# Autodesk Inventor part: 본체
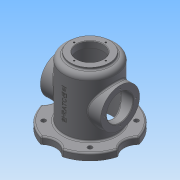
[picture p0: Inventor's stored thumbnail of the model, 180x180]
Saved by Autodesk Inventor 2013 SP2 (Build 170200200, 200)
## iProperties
Created: 2026-07
Part Number: 본체
Material: Generic
Document SubType Name: Modeling
Designer: a
Density: 1 g/cm^3
Mass: 556.956 g
Surface Area: 1242.71 cm^2
Volume: 556.956 cm^3
Author: a
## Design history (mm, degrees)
sketch "스케치1"
  geometry: L1 (100, 0)-(-100, 0); L2 (0, -100)-(0, 100); A1 r 30 centre (100, 0) between (79.12, -21.541) and (79.12, 21.541); A2 r 30 centre (0, 100) between (-21.541, 79.12) and (21.541, 79.12); A3 r 30 centre (-100, 0) between (-79.12, -21.541) and (-79.12, 21.541); A4 r 30 centre (0, -100) between (21.541, -79.12) and (-21.541, -79.12); A5 r 82 centre (0, 0) between (21.541, -79.12) and (79.12, -21.541); A6 r 82 centre (0, 0) between (-79.12, -21.541) and (-21.541, -79.12); A7 r 82 centre (0, 0) between (79.12, 21.541) and (21.541, 79.12); A8 r 82 centre (0, 0) between (-21.541, 79.12) and (-79.12, 21.541); 3 further points
  constraints: 16 point on circle, 8 centre point, 4 coincident, 4 end point, 4 midpoint, 1 horizontal, 1 perpendicular, 9 other
  dimensions: "d1" = 200 distance of L1.start L1.end; "d2" = 200 distance of L2.start L2.end; "d3" = 60 diameter of A1; "d6" = 360 deg dimension on A5.centre A1.centre (derived); "d8" = 82 radius of A5; "d9" = 82 radius of A6; "d10" = 82 radius of A8; "d11" = 82 radius of A7
extrude "돌출1" new body sketch "스케치1" distance "d12" = 14; taper "d13" = 0 deg
sketch "스케치2"
  geometry: C1 r 53 at (0, 0); 1 further point
  constraints: 1 centre point, 1 coincident
  dimensions: "d14" = 106 diameter of C1
extrude "돌출2" join sketch "스케치2" distance "d15" = 132; taper "d16" = 0 deg
sketch "스케치3"
  geometry: C1 r 53 at (0, 0) reference; C2 r 40 at (0, 0)
  constraints: 1 centre point, 1 coincident
  dimensions: "d17" = 80 diameter of C2
extrude "돌출3" join sketch "스케치3" distance "d18" = 5; taper "d19" = 0 deg
sketch "스케치4"
  geometry: L1 (-70, 0)-(-70, 14) reference; L2 (-70, 14)-(-53, 14) reference; L3 (-53, 14)-(-53, 132) reference; L4 (-53, 132)-(-40, 132) reference; L5 (-40, 132)-(-40, 137) reference; L6 (-40, 137)-(40, 137) reference; L7 (40, 137)-(40, 132) reference; L8 (40, 132)-(53, 132) reference; L9 (53, 132)-(53, 14) reference; L10 (53, 14)-(70, 14) reference; L11 (70, 14)-(70, 0) reference; L12 (70, 0)-(-70, 0) reference; L13 (-62, 68)-(62, 68); L14 (-62, 68)-(-62, 108); L15 (-62, 108)-(62, 108); L16 (62, 108)-(62, 68); 3 further points
  constraints: 8 end point, 2 midpoint, 2 parallel, 2 perpendicular, 1 vertical alignment
  dimensions: "d20" = 68 distance from line of point (0, 0) L13; "d21" = 124 distance of L13.start L13.end; "d22" = 80 diameter of L15 L13
revolve "회전1" sketch "스케치4" stored, may be unused: angle "d23" = 90 deg
sketch "스케치5"
  geometry: L1 (-70, 0)-(-70, 14) reference; L2 (-70, 14)-(-53, 14) reference; L3 (-53, 14)-(-53, 28) reference; L4 (-53, 28)-(-62, 28) reference; L5 (-62, 28)-(-62, 108) reference; L6 (-62, 108)-(-53, 108) reference; L7 (-53, 108)-(-53, 132) reference; L8 (-53, 132)-(-40, 132) reference; L9 (-40, 132)-(-40, 137) reference; L10 (-40, 137)-(40, 137) reference; L11 (40, 137)-(40, 132) reference; L12 (40, 132)-(53, 132) reference; L13 (53, 132)-(53, 108) reference; L14 (53, 108)-(62, 108) reference; L15 (62, 108)-(62, 28) reference; L16 (62, 28)-(53, 28) reference; L17 (53, 28)-(53, 14) reference; L18 (53, 14)-(70, 14) reference; L19 (70, 14)-(70, 0) reference; L20 (70, 0)-(-70, 0) reference; L21 (0, 0)-(0, 137); L22 (-27, 137)-(-27, 124); L23 (-27, 124)-(-42, 124); L24 (-45, 121)-(-45, 0); L25 (-27, 137)-(0, 137); L26 (-45, 0)-(0, 0); A1 r 3 centre (-42, 121) between (-42, 124) and (-45, 121)
  constraints: 12 end point, 2 perpendicular, 2 point on circle, 2 point on line, 2 tangent, 1 centre point, 1 collinear, 1 midpoint, 1 parallel, 1 vertical
  dimensions: "d24" = 54 diameter of L22 L21; "d26" = 90 diameter of L24 L21; "d27" = 124 distance between parallel lines of L20 L23; "d28" = 3 radius of A1
revolve "회전2" sketch "스케치5" stored, may be unused: angle "d29" = 90 deg
chamfer "모따기1" distance "d30" = 1; stored, may be unused: second distance "d31" = 2, angle "d32" = 45 deg
sketch "스케치6"
  geometry: L1 (70, 14)-(70, 0) reference; L2 (70, 0)-(45, 0) reference; L3 (45, 0)-(45, 121) reference; L4 (42, 124)-(27, 124) reference; L5 (27, 124)-(27, 136) reference; L6 (27, 136)-(28, 137) reference; L7 (28, 137)-(40, 137) reference; L8 (40, 137)-(40, 132) reference; L9 (40, 132)-(53, 132) reference; L10 (53, 132)-(53, 108) reference; L11 (53, 108)-(62, 108) reference; L12 (62, 108)-(62, 28) reference; L13 (62, 28)-(53, 28) reference; L14 (53, 28)-(53, 14) reference; L15 (53, 14)-(70, 14) reference; L16 (-70, 0)-(-70, 14) reference; L17 (-70, 14)-(-53, 14) reference; L18 (-53, 14)-(-53, 28) reference; L19 (-53, 28)-(-62, 28) reference; L20 (-62, 28)-(-62, 108) reference; L21 (-62, 108)-(-53, 108) reference; L22 (-53, 108)-(-53, 132) reference; L23 (-53, 132)-(-40, 132) reference; L24 (-40, 132)-(-40, 137) reference; L25 (-40, 137)-(-28, 137) reference; L26 (-28, 137)-(-27, 136) reference; L27 (-27, 136)-(-27, 124) reference; L28 (-27, 124)-(-42, 124) reference; L29 (-45, 121)-(-45, 0) reference; L30 (-45, 0)-(-70, 0) reference; L31 (-62, 68)-(62, 68); L32 (-62, 68)-(-62, 95); L33 (-62, 95)-(62, 95); L34 (62, 95)-(62, 68); A1 r 3 centre (42, 121) between (45, 121) and (42, 124) reference; A2 r 3 centre (-42, 121) between (-42, 124) and (-45, 121) reference; 1 further point
  constraints: 8 end point, 2 midpoint, 2 point on line, 1 collinear, 1 perpendicular
  dimensions: "d33" = 54 diameter of L33 L31
revolve "회전3" sketch "스케치6" stored, may be unused: angle "d34" = 90 deg
fillet "모깎기1" dims "d35" = 3
fillet "모깎기2" dims "d36" = 10
sketch "스케치7" dims "d37" = 135
  geometry: L1 (0, 0)-(-92.353, 92.353); L2 (0, 0)-(0, 100); L3 (0, 0)-(92.353, 92.353); L4 (-100, 0)-(100, 0); C1 r 53 at (0, 0) reference; C2 r 45 at (0, 0) reference; C3 r 4.5 at (-47.73, 47.73); C4 r 4.5 at (47.73, 47.73); C5 r 4.5 at (-47.73, -47.73); C6 r 4.5 at (47.73, -47.73); A1 r 82 centre (0, 0) between (-21.541, 79.12) and (-79.12, 21.541) reference; A2 r 30 centre (0, 100) between (-21.541, 79.12) and (21.541, 79.12) reference; A3 r 82 centre (0, 0) between (79.12, 21.541) and (21.541, 79.12) reference; A4 r 30 centre (100, 0) between (79.12, 21.541) and (79.12, -21.541) reference; A5 r 82 centre (0, 0) between (21.541, -79.12) and (79.12, -21.541) reference; A6 r 30 centre (0, -100) between (21.541, -79.12) and (-21.541, -79.12) reference; A7 r 82 centre (0, 0) between (-79.12, -21.541) and (-21.541, -79.12) reference; A8 r 30 centre (-100, 0) between (-79.12, -21.541) and (-79.12, 21.541) reference
  constraints: 8 end point, 4 centre point, 4 symmetric about line, 1 coincident, 1 perpendicular, 1 point on line, 1 vertical, 6 other
  dimensions: "d38" = 45 deg angle of L2 L1; "d40" = 9 diameter of C3
extrude "돌출4" cut sketch "스케치7" stored distance "d41" = 5; taper "d42" = 0 deg
chamfer "모따기2" distance "d43" = 1; stored, may be unused: second distance "d44" = 2, angle "d45" = 45 deg
sketch "스케치8" dims "d46" = 65
  geometry: L1 (0, 0)-(0, 32.5); C1 r 28 at (0, 0) reference; C2 r 40 at (0, 0) reference; 4 further points
  constraints: 2 coincident, 2 end point, 1 vertical, 1 vertical alignment, 7 other
  dimensions: "d49" = 360 deg dimension on L1.start point (0, 32.5) (derived)
hole "구멍1" sketch "스케치8" at (0, 32.5), (-32.5, 0), (0, -32.5), (32.5, 0) diameter "d51" = 3.242; stored, may be unused: countersink angle "d55" = 90 deg, drill point angle "d57" = 118 deg; dims "d52" = 8, "d53" = 4, "d54" = 2, "d56" = 10
sketch "스케치9" dims "d58" = 65
  geometry: L1 (-53.666, -68)-(-53.666, -54) reference; L2 (-53.666, -54)-(53.666, -54) reference; L3 (53.666, -54)-(53.666, -68) reference; L4 (53.666, -68)-(-53.666, -68) reference; L5 (0, 0)-(0, 32.5); C1 r 28 at (0, 0) reference; C2 r 40 at (0, 0) reference; 5 further points
  constraints: 2 coincident, 2 end point, 1 perpendicular, 1 vertical alignment, 7 other
  dimensions: "d61" = 360 deg dimension on L5.start point (0, 32.5) (derived)
hole "구멍2" sketch "스케치9" at (0, 32.5), (-32.5, 0), (0, -32.5), (32.5, 0) diameter "d63" = 3.242; stored, may be unused: countersink angle "d67" = 90 deg, drill point angle "d69" = 118 deg; dims "d64" = 8, "d65" = 4, "d66" = 2, "d68" = 10
node "작업 평면1"
sketch "스케치10"
  geometry: L1 (-21.541, 0)-(21.541, 0) reference; 3 further points
  constraints: 1 midpoint, 1 vertical alignment, 1 other
  dimensions: "d70" = 70 distance of point (0, 0) point (0, 70)
feature "엠보싱1" sketch "스케치10" dims "d1" = 200, "d2" = 200, "d3" = 60, "d6" = 360 deg (derived), "d8" = 82, "d9" = 82, "d10" = 82, "d11" = 82, "d71" = 0.5, "d72" = 0
fillet "모깎기3" dims "d73" = 3
fillet "모깎기4" dims "d74" = 3
fillet "모깎기5" dims "d75" = 3
fillet "모깎기6" dims "d76" = 3
fillet "모깎기7" dims "d77" = 3
node "솔리드1"
mirror "대칭1"
node "절단 모서리 투영1"
node "절단 모서리 투영2"
node "절단 모서리 투영3"
node "절단 모서리 투영4"
node "절단 모서리 투영5"
node "절단 모서리 투영6"
other parameters: "d0" = 164
